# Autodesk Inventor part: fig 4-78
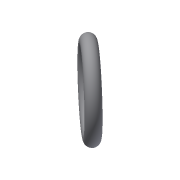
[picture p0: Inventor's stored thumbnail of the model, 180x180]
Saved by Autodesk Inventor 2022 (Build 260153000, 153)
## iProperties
Created: 2012-07
Part Number: fig 4-78
Material: Generic
Document SubType Name: Modeling
Designer: CADCIM
Density: 1 g/cm^3
Appearance: Default
Author: CADCIM
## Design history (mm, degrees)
sketch "Sketch1"
  geometry: L1 (-1.626, -1.876)-(1.626, 1.876); L2 (0, 0)-(7.504, -6.505); C1 r 1.845 at (7.504, -6.505)
  constraints: 4 end point, 1 centre point, 1 midpoint, 1 perpendicular
  dimensions: "d0" = 90 deg dimension on L2.end C1 L1.start L1.end L1 L2.start L2
revolve "Revolution1" sketch "Sketch1" stored, may be unused: angle "d0" = 90 deg
body "Solid1"
